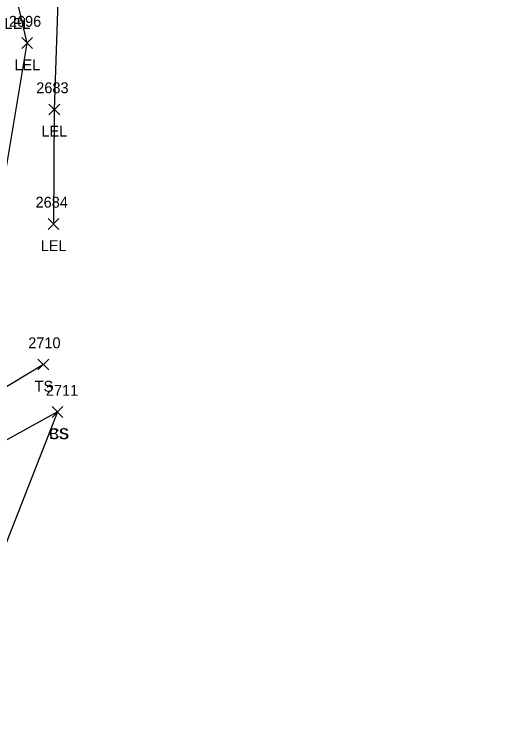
# Model space of a CAD drawing. Extents: x 1483143 to 1488182, y 802902 to 807581.
# Drawn here: x 1487613.8 to 1487705.3, y 805526.6 to 805656.4 of the extents above; entities that cross this region are included whole.
import ezdxf

# ---------------------------------------------------------------- set-up
doc = ezdxf.new("R2010")
doc.units = 0
for name, color, linetype in [('L_A', 7, 'Continuous'), ('L_I', 7, 'Continuous'), ('L_TIC', 7, 'Continuous'), ('LARO', 7, 'Continuous'), ('LELB', 7, 'Continuous')]:
    doc.layers.add(name, color=color, linetype=linetype)

msp = doc.modelspace()

# ---------------------------------------------------------------- linework, layer by layer
at = {"layer": 'L_TIC'}
for points in [[(1487615.21, 805650.1), (1487617.21, 805652.1)], [(1487617.21, 805650.1), (1487615.21, 805652.1)], [(1487620.2, 805637.86), (1487622.2, 805639.86)], [(1487622.2, 805637.86), (1487620.2, 805639.86)], [(1487620.06, 805616.78), (1487622.06, 805618.78)], [(1487622.06, 805616.78), (1487620.06, 805618.78)], [(1487618.19, 805590.89), (1487620.19, 805592.89)], [(1487620.19, 805590.89), (1487618.19, 805592.89)], [(1487620.79, 805582.15), (1487622.79, 805584.15)], [(1487622.79, 805582.15), (1487620.79, 805584.15)], [(1487620.79, 805582.15), (1487622.79, 805584.15)], [(1487622.79, 805582.15), (1487620.79, 805584.15)]]:
    msp.add_lwpolyline(points, dxfattribs=at)
at = {"layer": 'LARO'}
for points in [[(1487705.29, 805896.34), (1487695.87, 805891.2), (1487689.13, 805878.29), (1487689.57, 805859.67), (1487670.44, 805829.21), (1487659.71, 805823.79), (1487649.08, 805803.93), (1487638.97, 805785.42), (1487633.21, 805776.22), (1487626.14, 805756.53), (1487619.37, 805736.85), (1487617.73, 805704.95), (1487625.22, 805691.16), (1487634.64, 805682.02), (1487622.34, 805673.38), (1487621.2, 805638.86), (1487621.06, 805617.78)], [(1487610.84, 805619.03), (1487616.21, 805651.1), (1487614.41, 805658.71), (1487614.34, 805675.89), (1487612.22, 805686.41), (1487589.81, 805683.79), (1487588.41, 805665.04), (1487589.09, 805646.88), (1487587.23, 805619.42), (1487592.18, 805594.63), (1487596.26, 805581.06)]]:
    msp.add_lwpolyline(points, dxfattribs=at)
at = {"layer": 'LELB'}
for points in [[(1487619.19, 805591.89), (1487593.27, 805576.26), (1487587.44, 805577.33), (1487576.69, 805573.73), (1487575.17, 805588.99), (1487571.23, 805601.64), (1487567.95, 805623.9), (1487571.74, 805641.94)], [(1487621.79, 805583.15), (1487609.04, 805550.72), (1487598.22, 805528.65), (1487588.58, 805526.63), (1487585.69, 805531.9), (1487587.81, 805544.19), (1487588.44, 805552.48), (1487583.03, 805549.53), (1487577.82, 805526.65)], [(1487621.79, 805583.15), (1487590.58, 805565.95)]]:
    msp.add_lwpolyline(points, dxfattribs=at)

# ---------------------------------------------------------------- texts
at = {"layer": 'L_A'}
for s, p in [('LEL', (1487612.05, 805653.71)), ('LEL', (1487613.85, 805646.1)), ('LEL', (1487618.84, 805633.86)), ('LEL', (1487618.7, 805612.78)), ('TS', (1487617.59, 805586.89)), ('CS', (1487620.23, 805578.15)), ('BS', (1487620.23, 805578.15))]:
    msp.add_text(s, height=2, dxfattribs=at).set_placement(p)
at = {"layer": 'L_I'}
for s, p in [('2696', (1487612.85, 805654.1)), ('2683', (1487617.89, 805641.86)), ('2684', (1487617.76, 805620.78)), ('2710', (1487616.41, 805594.89)), ('2711', (1487619.67, 805586.15)), ('2711', (1487619.67, 805586.15))]:
    msp.add_text(s, height=2, dxfattribs=at).set_placement(p)

doc.saveas('drawing.dxf')
